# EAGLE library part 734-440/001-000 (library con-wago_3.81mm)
Serie 734, Doppelstock-Stiftleisten Einlötstift abgewinkelt 1 x 1 mm / Series 734, Double-deck male headers Angled solder pin 1 x 1 mm Polzahl / Pole No.: 10 Rastermaß / Pitch: 3.81 mm Bemessungsspannung / Rated Voltage: 160 V Nennstrom / Nominal Current: 10 A Lötstiftlänge: / Solder Pin Length: 3.6 mm Farbe / Color: orange / orange Stand: 01.01.2012. Die jeweils aktuellen Daten zu diesem Artikel finden Sie in unserem Produktkatalog, den Sie unter www.wago.com einsehen können. As of: 01/01/2012. Please find the newest data for this article in our product catalogue, which can be viewed under www.wago.com.
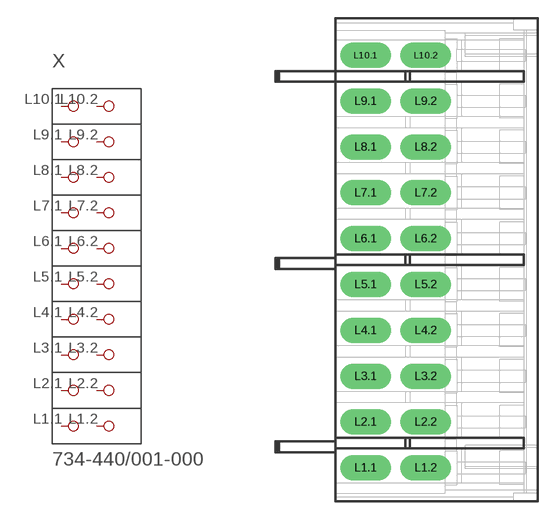
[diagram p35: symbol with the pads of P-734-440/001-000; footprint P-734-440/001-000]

Designator prefix X

## 734-440/001-000  [P-734-440/001-000]
L1.1  P1.1
L1.2  P1.2
L2.1  P2.1
L2.2  P2.2
L3.1  P3.1
L3.2  P3.2
L4.1  P4.1
L4.2  P4.2
L5.1  P5.1
L5.2  P5.2
L6.1  P6.1
L6.2  P6.2
L7.1  P7.1
L7.2  P7.2
L8.1  P8.1
L8.2  P8.2
L9.1  P9.1
L9.2  P9.2
L10.1  P10.1
L10.2  P10.2

## Footprint P-734-440/001-000 (pad centres in mm)
drill 1.4 long: L1.1 -3.4,-17.295; L1.2 1.6,-17.295; L2.1 -3.4,-13.485; L2.2 1.6,-13.485; L3.1 -3.4,-9.685; L3.2 1.6,-9.685; L4.1 -3.4,-5.875; L4.2 1.6,-5.875; L5.1 -3.4,-2.055; L5.2 1.6,-2.055; L6.1 -3.4,1.755; L6.2 1.6,1.755; L7.1 -3.4,5.565; L7.2 1.6,5.565; L8.1 -3.4,9.375; L8.2 1.6,9.375; L9.1 -3.4,13.185; L9.2 1.6,13.185; L10.1 -3.4,16.995; L10.2 1.6,16.995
